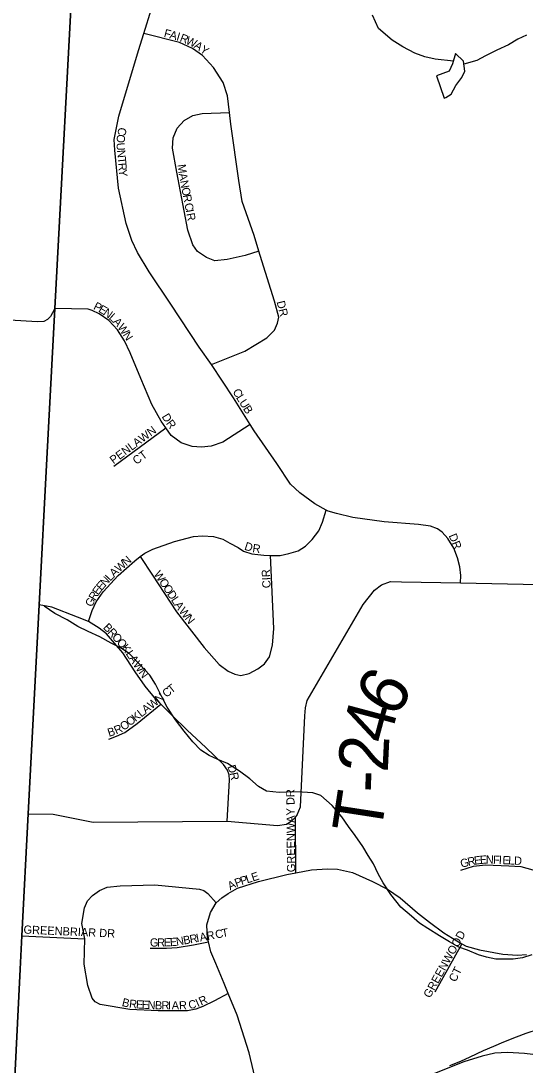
# Model space of a CAD drawing. Extents: x 1759416 to 2214760, y 252598 to 1116833.
# Drawn here: x 2005444 to 2008511, y 885483 to 891835 of the extents above; entities that cross this region are included whole.
import ezdxf

# ---------------------------------------------------------------- set-up
doc = ezdxf.new("R2010")
doc.units = 0
for name, color, linetype in [('GM_X_County_Road', 7, 'Continuous'), ('GM_X_County_Subdivision', 7, 'Continuous'), ('GM_X_County_Subdivision_Text', 7, 'Continuous'), ('GM_X_Minor_Lake', 7, 'Continuous'), ('GM_X_Minor_River', 7, 'Continuous'), ('GM_X_Township', 7, 'Continuous'), ('GM_X_Township_Road', 7, 'Continuous'), ('GM_X_Township_Road_Text', 7, 'Continuous'), ('GM_X_Township_Subdivision', 7, 'Continuous'), ('GM_X_Township_Subdivision_Text', 7, 'Continuous')]:
    doc.layers.add(name, color=color, linetype=linetype)

msp = doc.modelspace()

# ---------------------------------------------------------------- linework, layer by layer
at = {"layer": 'GM_X_County_Road'}
msp.add_lwpolyline([(2004887.1, 877838.9), (2004966.1, 878054.7), (2005006.3, 878210), (2005059.3, 878425.5), (2005076, 878622.8), (2005114.2, 879911.6), (2005203.2, 881311.9), (2005266.8, 882813.7), (2005306.3, 883397.6), (2005439.1, 886066.7), (2005449.8, 886268.9), (2005489.1, 887010.5), (2005555.5, 888282.1), (2005602.6, 889171.2), (2005650.9, 890084.8), (2005769.6, 892327), (2005807.5, 893043.9), (2005864.5, 894121.1), (2005998.4, 896652.4), (2006004, 896754.8), (2006008, 896849.4)], dxfattribs=at)
at = {"layer": 'GM_X_County_Subdivision'}
msp.add_lwpolyline([(2006886, 885333.8), (2006832.6, 885557.9), (2006759.1, 885785.9), (2006705.2, 885917.8), (2006679.8, 885979.8), (2006629, 886099.8), (2006600.5, 886171.7), (2006585.2, 886233), (2006580, 886253.8), (2006575.5, 886335.9), (2006597.1, 886410.2), (2006632.7, 886470.5), (2006666.6, 886500.8), (2006704.5, 886527), (2006762.4, 886559.4), (2006890.2, 886600.3), (2007062.2, 886641.3), (2007115.8, 886651.7), (2007212.2, 886670.3), (2007308.2, 886676.9), (2007370.3, 886675.2), (2007460.5, 886653.7), (2007583, 886600.3), (2007673.4, 886552.8), (2007751.8, 886501.1), (2007856.5, 886409.5), (2007928.9, 886351.9), (2008017.4, 886288.3), (2008095.8, 886238.6), (2008126.5, 886221.3), (2008152, 886206.9), (2008234.3, 886183.3), (2008374.6, 886158.1), (2008464.7, 886150.6), (2008518.8, 886155)], dxfattribs=at)
at = {"layer": 'GM_X_Minor_Lake'}
for points in [[(2008087.4, 891636.3), (2008069.6, 891574.1), (2008049.7, 891529.9), (2007971.7, 891501.6), (2008018.3, 891365.5), (2008028.3, 891369.5), (2008060.3, 891389.7), (2008090.1, 891441.9), (2008126, 891490.1), (2008143.9, 891530.3), (2008135.6, 891590.4)], [(2008135.6, 891590.4), (2008087.4, 891636.3)]]:
    msp.add_lwpolyline(points, dxfattribs=at)
at = {"layer": 'GM_X_Minor_River'}
for points in [[(2008074.4, 891590.9), (2007963.3, 891601.8), (2007901.2, 891617.6), (2007841, 891639.4), (2007766.8, 891677.3), (2007702.5, 891717.1), (2007620.1, 891789), (2007581.8, 891871.1)], [(2008519.6, 891748), (2008465.6, 891723.8), (2008409.6, 891689.5), (2008339.7, 891657.2), (2008269.7, 891622.9), (2008217.7, 891594.6), (2008138.1, 891572.1)], [(2008550.9, 886154.3), (2008494.9, 886136.1), (2008438.8, 886127.9), (2008332.7, 886127.5), (2008276.6, 886139.3), (2008226.5, 886153.2), (2008160.3, 886181), (2008108.1, 886200.9), (2008051.9, 886232.8), (2007989.7, 886268.6), (2007919.4, 886314.5), (2007869.2, 886346.4), (2007819, 886388.3), (2007754.7, 886444.2), (2007694.3, 886520.1), (2007648, 886592.1), (2007617.7, 886646.1), (2007589.5, 886706.2), (2007557.2, 886758.2), (2007523, 886812.2), (2007476.6, 886880.2), (2007436.4, 886934.1), (2007396.1, 886992.1), (2007337.8, 887062.1), (2007269.4, 887121.9), (2007219.3, 887139.8), (2007155.2, 887143.6), (2007099.1, 887145.4), (2007015, 887141.1), (2006938.9, 887148.9), (2006888.7, 887176.8), (2006836.4, 887224.7), (2006774.2, 887270.6), (2006699.9, 887318.4), (2006641.7, 887342.3), (2006589.5, 887366.1), (2006539.4, 887398), (2006491.1, 887450), (2006436.8, 887513.9), (2006384.4, 887583.9), (2006334.1, 887659.9), (2006301.8, 887723.9), (2006263.4, 887799.9), (2006229.2, 887853.9), (2006164.8, 887921.8), (2006102.5, 887985.8), (2006050.3, 888021.7), (2005994.1, 888049.5), (2005923.9, 888087.4), (2005853.6, 888121.2), (2005791.4, 888151), (2005725.2, 888190.9), (2005650.9, 888230.7), (2005586.7, 888274.6)], [(2008716.9, 885691.9), (2008664.8, 885707.8), (2008590.7, 885699.5), (2008514.7, 885675.2), (2008456.7, 885652.9), (2008378.7, 885622.6), (2008318.7, 885596.3), (2008256.7, 885570.1), (2008174.7, 885531.7), (2008118.8, 885505.5), (2008050.8, 885477.2)]]:
    msp.add_lwpolyline(points, dxfattribs=at)
at = {"layer": 'GM_X_Township'}
for points in [[(1998107.8, 897126.5), (1999328.7, 897063.4), (2003204.9, 896913.2), (2006004, 896754.8), (2005998.4, 896652.4), (2005864.5, 894121.1), (2005807.5, 893043.9), (2005769.6, 892327), (2005650.9, 890084.8), (2005602.6, 889171.2), (2005555.5, 888282.1), (2005489.1, 887010.5), (2005449.8, 886268.9), (2005439.1, 886066.7), (2005306.3, 883397.6)], [(2005306.3, 883397.6), (2005439.1, 886066.7), (2005449.8, 886268.9), (2005489.1, 887010.5), (2005555.5, 888282.1), (2005602.6, 889171.2), (2005650.9, 890084.8), (2005769.6, 892327), (2005807.5, 893043.9), (2005864.5, 894121.1), (2005998.4, 896652.4), (2010326.5, 896491.5), (2011122.5, 896461.9), (2011648.1, 896428), (2012134.2, 896416.9), (2013353.6, 896345), (2014249.7, 896310.5), (2015226.5, 896288.6), (2016682.3, 896255.5), (2022025.3, 896071.6)]]:
    msp.add_lwpolyline(points, dxfattribs=at)
at = {"layer": 'GM_X_Township_Road'}
for points in [[(2005650.9, 890084.8), (2005625.1, 890036.8), (2005607, 890018.8), (2005583, 890006.8), (2005543, 890004.9), (2004908.7, 890043.7), (2003950.2, 890088.8), (2003258.6, 890138.4), (2002384.6, 890184.3)], [(2007125.4, 887005.7), (2007145.7, 887054.6), (2007170.3, 887607.9), (2007176, 887656), (2007185.8, 887700.1), (2007526.6, 888285.3), (2007594.1, 888371.8), (2007637.9, 888404.2), (2007691.9, 888424.5), (2007758.3, 888423.2)], [(2007758.3, 888423.2), (2008118.3, 888415.8), (2009163.7, 888395.1)], [(2005489.1, 887010.5), (2005640, 887009.7), (2005884.9, 886961.1), (2006697.9, 886967.3), (2007004.3, 886939.6), (2007060.3, 886947.9), (2007094.2, 886970.2), (2007114.3, 886992), (2007124, 887002.4), (2007125.4, 887005.7)]]:
    msp.add_lwpolyline(points, dxfattribs=at)
at = {"layer": 'GM_X_Township_Subdivision'}
for points in [[(2008118.3, 888415.8), (2008120.1, 888461.1), (2008113.8, 888513.2), (2008099.4, 888569.2), (2008077.1, 888627.2), (2008040.6, 888687.1), (2008006.4, 888725), (2007978.2, 888744.8), (2007936.1, 888760.6), (2007861.9, 888772.2), (2007653.6, 888787), (2007463.2, 888813.9), (2007362.9, 888839.4), (2007312.8, 888853.1), (2007301.3, 888859.4), (2007232.5, 888896.7), (2007139.9, 888964.3), (2007083.6, 889016.1), (2007000.7, 889141.9), (2006863.3, 889341.5), (2006839.4, 889380), (2006737.9, 889543.1), (2006604.6, 889744.7), (2006527.8, 889850.5), (2006356, 890112), (2006224.7, 890309.6), (2006153.9, 890425.5), (2006119.4, 890499.4), (2006084.7, 890603.4), (2006037.3, 890817.5), (2006015.9, 891047.9), (2006011.5, 891113.9), (2006040.6, 891256.4), (2006160.3, 891655.9), (2006192, 891758), (2006238.8, 891908.8)], [(2006604.6, 889744.7), (2006806.3, 889826.1), (2006939.9, 889907), (2006987.7, 889953.4), (2007005.5, 889995.6), (2007013.2, 890033.7), (2006986.6, 890129.7), (2006909, 890375.7), (2006892, 890433.9), (2006864, 890529.8), (2006790.7, 890735.8), (2006769.8, 890863.9), (2006721.7, 891206.3), (2006712.9, 891277.5), (2006700.6, 891378.5), (2006674.1, 891460.5), (2006615.4, 891552.4), (2006548.9, 891624.1), (2006488.6, 891667.8), (2006408.3, 891703.4), (2006192, 891758)], [(2006892, 890433.9), (2006808.7, 890407.2), (2006698.7, 890384.5), (2006624.7, 890376.1), (2006572.5, 890395.8), (2006518.2, 890431.6), (2006490, 890473.5), (2006459.4, 890561.5), (2006393.1, 890915.8), (2006366.2, 891061.9), (2006369.8, 891124.1), (2006395.5, 891182.3), (2006437.2, 891228.7), (2006491.1, 891259), (2006547.1, 891271.4), (2006712.9, 891277.5)], [(2006839.4, 889380), (2006673.5, 889272.2), (2006601.6, 889247.7), (2006543.6, 889241.4), (2006485.5, 889245.1), (2006419.3, 889268.7), (2006358.9, 889312.4), (2006325.8, 889360.5), (2006298.3, 889400.3), (2006241.7, 889502.1), (2006174.6, 889660.1), (2006109.6, 889816), (2006075.1, 889887.9), (2006032.6, 889955.8), (2005980.2, 890011.6), (2005919.9, 890053.3), (2005877.7, 890073.1), (2005853.7, 890081), (2005650.9, 890084.8)], [(2006009.7, 889126), (2006325.8, 889360.5)], [(2005855, 888181.4), (2005877, 888247.5), (2005902.7, 888301.8), (2005944.3, 888362.2), (2006035.9, 888460.9), (2006137.4, 888549.7), (2006170.2, 888576.2), (2006197.2, 888598.1), (2006247.1, 888622.4), (2006379, 888667.3), (2006494.9, 888698), (2006548.9, 888702.4), (2006615, 888698.7), (2006673.2, 888683.1), (2006715.4, 888657.2), (2006765.6, 888631.5), (2006797.8, 888609.6), (2006847.9, 888593.9), (2006922.1, 888584.3), (2006962.3, 888583.8), (2007022.2, 888582.9), (2007074.1, 888595.2), (2007130.1, 888611.6), (2007176, 888639.9), (2007215.8, 888680.2), (2007255.5, 888732.6), (2007279.2, 888784.8), (2007301.3, 888859.4)], [(2006170.2, 888576.2), (2006244.1, 888464.1), (2006391.6, 888240.5), (2006559.1, 888023.1), (2006649.9, 887919.4), (2006704.2, 887879.7), (2006746.3, 887861.9), (2006782.4, 887852.1), (2006832.4, 887864.4), (2006886.3, 887892.7), (2006926.1, 887923.1), (2006955.9, 887967.3), (2006975.5, 888037.6), (2006982.9, 888137.8), (2006962.3, 888583.8)], [(2006697.9, 886967.3), (2006712.3, 887216.4), (2006710.1, 887248.5), (2006701.9, 887276.5), (2006675.6, 887312.4), (2006568.9, 887413.9), (2006456.1, 887519.5), (2006363.4, 887609.1), (2006313.1, 887661), (2006294.9, 887678.9), (2006264.7, 887708.8), (2006200.2, 887788.5), (2006139.6, 887874.3), (2006064.8, 887990.1), (2006014.4, 888049.9), (2005965.9, 888105.8), (2005919.7, 888141.6), (2005855, 888181.4), (2005789.1, 888206.9), (2005632.4, 888269.2), (2005555.5, 888282.1)], [(2005979.9, 887464.6), (2006025.8, 887482.9), (2006075.8, 887505.2), (2006151.5, 887561.8), (2006294.9, 887678.9)], [(2007115.8, 886651.7), (2007114.3, 886992)], [(2008119.1, 886667.6), (2008197.1, 886692.1), (2008269.1, 886700.6), (2008411.3, 886695.4), (2008485.4, 886691.8), (2008557.6, 886670.2), (2008671.9, 886636.8), (2008780.3, 886595.3), (2008883.1, 886537.8)], [(2006705.2, 885917.8), (2006622.4, 885873.3), (2006550.5, 885838.8), (2006508.6, 885822.5), (2006458.6, 885812.2), (2006278.4, 885813.1), (2006106.2, 885820.1), (2005925.8, 885851.1), (2005895.7, 885867), (2005877.5, 885888.9), (2005851, 885966.9), (2005830.2, 886097), (2005833.8, 886251.6), (2005814.6, 886343.4), (2005832.1, 886439.7), (2005849.8, 886481.9), (2005879.6, 886514.1), (2005921.5, 886544.5), (2005969.4, 886564.8), (2006047.5, 886573.3), (2006259.7, 886578.5), (2006530.1, 886552), (2006556.2, 886544.2), (2006580.3, 886526.3), (2006632.7, 886470.5)], [(2005449.8, 886268.9), (2005833.8, 886251.6)], [(2006230, 886193.6), (2006330.1, 886194.2), (2006394.1, 886198.6), (2006494.2, 886215.2), (2006585.2, 886233)], [(2008126.5, 886221.3), (2007961.5, 885927.2)], [(2009146.3, 885427.8), (2009014.7, 885485), (2008906.8, 885509.9), (2008694.8, 885531.8), (2008506.8, 885553.4), (2008404.7, 885560.2), (2008326.6, 885554.9), (2008250.4, 885537.5), (2008138, 885502.4), (2007690.1, 885323.8)]]:
    msp.add_lwpolyline(points, dxfattribs=at)

# ---------------------------------------------------------------- texts
at = {"layer": 'GM_X_County_Subdivision_Text'}
for s, rotation, p in [('A', 27.36661, (2006717, 886545.7)), ('P', 20.28423, (2006754.6, 886565.2)), ('P', 17.53653, (2006787, 886577.2)), ('L', 17.39803, (2006820.6, 886587.8)), ('E', 18.6643, (2006855.3, 886598.7))]:
    msp.add_text(s, height=50, rotation=rotation, dxfattribs=at).set_placement(p)
at = {"layer": 'GM_X_Township_Road_Text'}
for s, rotation, p in [('6', 59.09514, (2007720.7, 887585.8)), ('4', 75.03606, (2007681.6, 887427.5)), ('2', 87.25115, (2007675.3, 887259.6)), ('-', 87.65945, (2007670.3, 887137.1)), ('T', 81.24927, (2007632.7, 886878.9))]:
    msp.add_text(s, height=300, rotation=rotation, dxfattribs=at).set_placement(p)
at = {"layer": 'GM_X_Township_Subdivision_Text'}
for s, rotation, p in [('F', 345.2481, (2006310.7, 891738.7)), ('A', 345.23753, (2006344.7, 891729.8)), ('I', 343.47236, (2006386.8, 891718.7)), ('R', 338.49172, (2006406.9, 891712.8)), ('W', 334.42751, (2006442.8, 891698.6)), ('A', 326.07351, (2006492.8, 891674.9)), ('Y', 324.15743, (2006528.9, 891650.6)), ('C', 257.83738, (2006040.3, 891190.7)), ('O', 262.32755, (2006031.2, 891147.8)), ('U', 274.81406, (2006025, 891092.3)), ('N', 275.11989, (2006028.8, 891048.1)), ('T', 275.1153, (2006032.7, 891004.3)), ('R', 275.12592, (2006035.8, 890969.3)), ('Y', 275.12122, (2006039.4, 890929.8)), ('M', 277.06629, (2006396.9, 890960.2)), ('A', 280.64821, (2006403.9, 890904.4)), ('N', 280.98401, (2006412.1, 890860.9)), ('O', 280.97553, (2006420.5, 890817.7)), ('R', 280.97176, (2006428.9, 890774.5)), ('C', 280.98635, (2006438.9, 890722.7)), ('I', 280.94992, (2006446.5, 890683.8)), ('R', 280.98635, (2006450.7, 890662.2)), ('P', 332.42086, (2005881.1, 890083.7)), ('E', 329.10651, (2005911.7, 890067.8)), ('DR', 284.03883, (2006999.4, 890125.9)), ('N', 324.51567, (2005941, 890050.3)), ('L', 317.12539, (2005975.5, 890025.8)), ('A', 312.20166, (2006000.5, 890002.7)), ('W', 305.62564, (2006029.1, 889971.3)), ('N', 302.45947, (2006062, 889925.4)), ('C', 297.70539, (2006730.5, 889582)), ('L', 301.69896, (2006750.8, 889543.6)), ('U', 302.43724, (2006769.6, 889513.1)), ('B', 302.4644, (2006793.3, 889475.9)), ('D', 300.82131, (2006299, 889428.5)), ('R', 306.57664, (2006324.5, 889386.2)), ('PENLAWN', 36.70295, (2006007.9, 889136.8)), ('CT', 36.24247, (2006146.8, 889133.4)), ('DR', 292.40725, (2008045, 888704.1)), ('D', 342.91977, (2006800, 888618.8)), ('R', 352.13045, (2006850.5, 888604)), ('N', 41.08724, (2006085.6, 888516.5)), ('W', 41.16852, (2006042.5, 888478.8)), ('N', 46.42205, (2005957.1, 888391.8)), ('L', 46.21723, (2005987.4, 888423.6)), ('A', 44.08816, (2006011.4, 888448.7)), ('W', 303.71805, (2006250.2, 888470)), ('CIR', 92.48833, (2006963.3, 888385.2)), ('E', 55.19598, (2005915.3, 888337.8)), ('E', 49.21498, (2005934.6, 888365.6)), ('O', 303.70826, (2006281.9, 888422.5)), ('O', 303.73031, (2006306.3, 888385.8)), ('G', 64.72556, (2005877.2, 888266)), ('R', 58.9238, (2005895.3, 888304.6)), ('D', 303.70826, (2006330.8, 888349.2)), ('L', 303.73192, (2006355.2, 888312.6)), ('A', 304.40824, (2006375.1, 888282.8)), ('W', 308.13612, (2006402.1, 888243.6)), ('N', 308.65718, (2006437.7, 888198.3)), ('B', 314.48477, (2005940.9, 888141.6)), ('R', 312.37171, (2005968.3, 888113.7)), ('O', 311.4121, (2005994.8, 888084.6)), ('O', 311.38125, (2006023.9, 888051.6)), ('K', 308.8373, (2006052.6, 888019)), ('L', 303.94011, (2006079.6, 887985.6)), ('A', 303.26576, (2006099.1, 887956.6)), ('W', 304.07594, (2006123.7, 887919.1)), ('N', 306.65775, (2006157.2, 887869.8)), ('N', 38.09786, (2006283.7, 887681)), ('C', 38.1106, (2006328.7, 887716.3)), ('T', 38.08819, (2006359.8, 887740.7)), ('W', 38.08734, (2006238.6, 887645.7)), ('K', 38.11371, (2006141.7, 887569.7)), ('L', 38.06668, (2006176.3, 887596.8)), ('A', 38.11371, (2006204, 887618.6)), ('R', 24.63141, (2006024.3, 887493.8)), ('O', 35.54984, (2006069.3, 887515.5)), ('O', 38.06614, (2006107, 887542.5)), ('B', 17.45976, (2005980.2, 887479.5)), ('D', 289.89348, (2006699.7, 887298.3)), ('R', 281.16708, (2006714.1, 887258.9)), ('GREENWAY DR', 90.56142, (2007112.9, 886656.3)), ('G', 13.90374, (2008123.2, 886683.1)), ('R', 11.39089, (2008165.4, 886693.6)), ('E', 7.58923, (2008203.3, 886701.3)), ('E', 4.86799, (2008237.6, 886705.9)), ('N', 358.95082, (2008271.3, 886708.8)), ('F', 357.43093, (2008314.9, 886708)), ('I', 357.45237, (2008350.1, 886706.4)), ('E', 357.45513, (2008372.1, 886705.4)), ('L', 357.45513, (2008407.3, 886703.9)), ('D', 357.15724, (2008442.4, 886702.3)), ('GREENBRIAR DR', 357.44329, (2005459.5, 886283)), ('I', 10.55518, (2006514.2, 886230.4)), ('A', 10.59081, (2006535.8, 886234.4)), ('R', 10.57639, (2006579.1, 886242.5)), ('C', 10.5765, (2006631, 886252.2)), ('T', 10.57489, (2006669.9, 886259.5)), ('GREENWOOD', 61.13297, (2007932.5, 885886.6)), ('G', 0.19674, (2006229.2, 886203.8)), ('R', 0.20772, (2006273.2, 886204)), ('E', 1.87716, (2006314.4, 886204.2)), ('E', 4.61895, (2006352.2, 886205.4)), ('N', 9.00557, (2006391.4, 886208.8)), ('B', 10.49258, (2006436.2, 886215.9)), ('R', 10.5765, (2006475.3, 886223.1)), ('CT', 63.43494, (2008088.4, 885984.2)), ('R', 25.9658, (2006541, 885844.4)), ('B', 346.79424, (2006055.6, 885842.7)), ('R', 353.70511, (2006100.6, 885832.6)), ('E', 357.03754, (2006143.2, 885828)), ('E', 357.08717, (2006178.3, 885826.1)), ('N', 357.08811, (2006213.5, 885824.4)), ('B', 358.59235, (2006258.9, 885822.1)), ('R', 0.04154, (2006299.8, 885821.1)), ('I', 0.28796, (2006339.7, 885821.1)), ('A', 0.28418, (2006361.7, 885821.2)), ('R', 0.30268, (2006405.7, 885821.5)), ('C', 10.05935, (2006467.7, 885823.5)), ('I', 25.02598, (2006520.2, 885834.7))]:
    msp.add_text(s, height=50, rotation=rotation, dxfattribs=at).set_placement(p)

doc.saveas('drawing.dxf')
